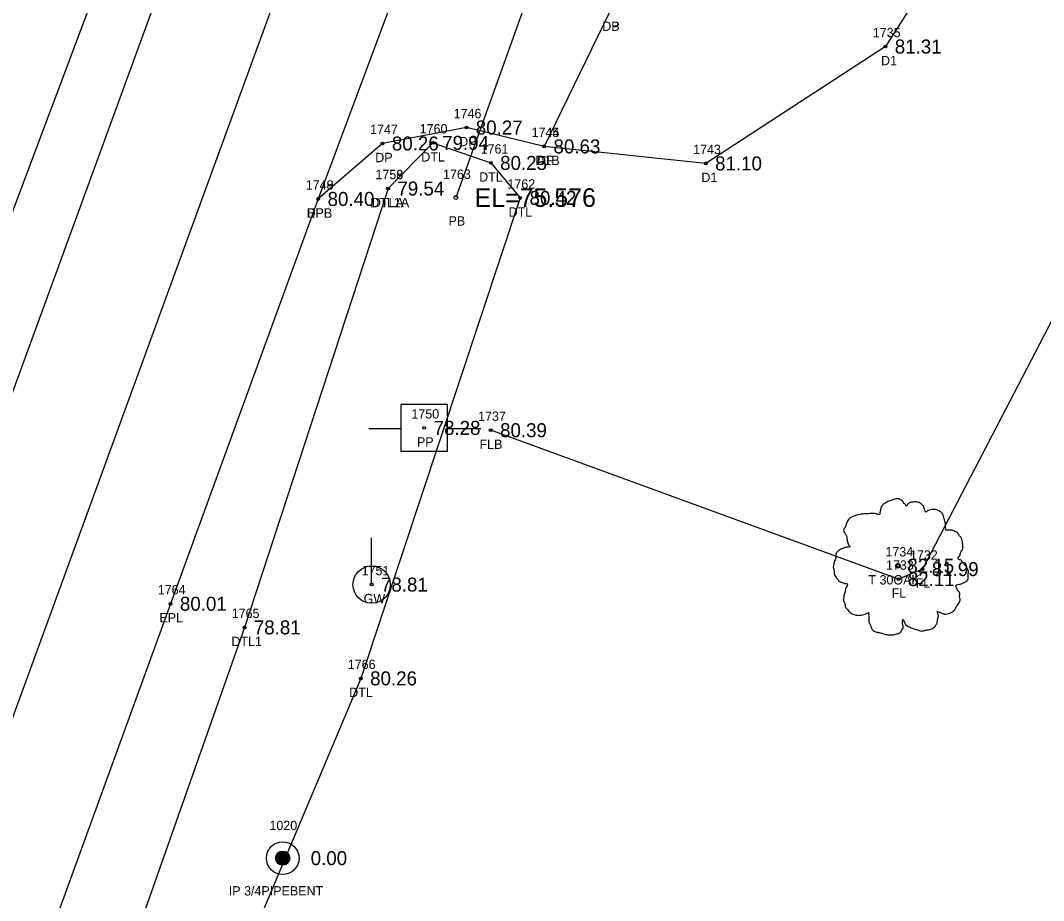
# Model space of a CAD drawing. Extents: x 2139392 to 2143384, y 505395 to 510520.
# Drawn here: x 2141070.2 to 2141179.8, y 509339.5 to 509433.7 of the extents above; entities that cross this region are included whole.
import ezdxf

# ---------------------------------------------------------------- set-up
doc = ezdxf.new("R2010")
doc.units = 0
for name, color, linetype in [('RD_EX_DR_Pipe', 7, 'Continuous'), ('RD_EX_DR_Pipe_txCode', 7, 'Continuous'), ('RD_EX_Driveway', 7, 'Continuous'), ('RD_EX_Driveway_txCode', 7, 'Continuous'), ('RD_EX_DV_Prop_txCode', 7, 'Continuous'), ('RD_EX_DV_PropPin', 7, 'Continuous'), ('RD_EX_Fence_Other', 7, 'Continuous'), ('RD_EX_Fence_Other_txCode', 7, 'Continuous'), ('RD_EX_H2O', 7, 'Continuous'), ('RD_EX_H2O_txCode', 7, 'Continuous'), ('RD_EX_Road', 7, 'Continuous'), ('RD_EX_Road_txCode', 7, 'Continuous'), ('RD_EX_TX_Driveway_ELEV', 7, 'Continuous'), ('RD_EX_TX_DV_Prop_ELEV', 7, 'Continuous'), ('RD_EX_TX_Fence_Other_ELEV', 7, 'Continuous'), ('RD_EX_TX_H2O_ELEV', 7, 'Continuous'), ('RD_EX_TX_Road_ELEV', 7, 'Continuous'), ('RD_EX_TX_UT_ELEV', 7, 'Continuous'), ('RD_EX_TX_VEG_ELEV', 7, 'Continuous'), ('RD_EX_UT', 7, 'Continuous'), ('RD_EX_UT_txCode', 7, 'Continuous'), ('RD_EX_VEG', 7, 'Continuous'), ('RD_EX_VEG_txCode', 7, 'Continuous'), ('RD_HC_Cl', 7, 'Continuous'), ('RD_HC_Survey_ELEV', 7, 'Continuous'), ('RD_SMD_Locator', 7, 'Continuous'), ('RD_TX_Pipe_ElevEX', 7, 'Continuous')]:
    doc.layers.add(name, color=color, linetype=linetype)

msp = doc.modelspace()

# ---------------------------------------------------------------- linework, layer by layer
at = {"layer": 'RD_EX_DR_Pipe'}
msp.add_line((2141127.21, 509443.68), (2141116.83, 509414.76), dxfattribs=at)
at = {"layer": 'RD_EX_Driveway'}
for points in [[(2141332.97, 509478.52), (2141281.25, 509505.33), (2141235.66, 509512.77), (2141218.34, 509505.03), (2141189.33, 509472.4), (2141162.86, 509430.93), (2141143.61, 509418.42), (2141126.3, 509420.24)], [(2141115.5, 509450.65), (2141123.22, 509439.59), (2141133.3, 509434.61), (2141126.3, 509420.24), (2141117.97, 509422.26), (2141108.98, 509420.55), (2141102.09, 509414.61)]]:
    msp.add_lwpolyline(points, dxfattribs=at)
at = {"layer": 'RD_EX_DV_PropPin'}
for p, q in [((2141098.07, 509343.3), (2141098.07, 509344.76)), ((2141098.11, 509343.29), (2141098.11, 509344.77)), ((2141098.14, 509343.28), (2141098.14, 509344.78)), ((2141098.18, 509343.28), (2141098.18, 509344.79)), ((2141098.21, 509343.27), (2141098.21, 509344.79)), ((2141098.25, 509343.27), (2141098.25, 509344.79)), ((2141098.28, 509343.27), (2141098.28, 509344.79)), ((2141098.32, 509343.27), (2141098.32, 509344.79)), ((2141098.35, 509343.27), (2141098.35, 509344.79)), ((2141098.39, 509343.28), (2141098.39, 509344.79)), ((2141098.42, 509343.28), (2141098.42, 509344.78)), ((2141098.46, 509343.29), (2141098.46, 509344.77)), ((2141098.49, 509343.3), (2141098.49, 509344.76)), ((2141097.55, 509343.84), (2141097.55, 509344.23)), ((2141097.58, 509343.73), (2141097.58, 509344.33)), ((2141097.62, 509343.66), (2141097.62, 509344.4)), ((2141097.65, 509343.61), (2141097.65, 509344.46)), ((2141097.69, 509343.56), (2141097.69, 509344.51)), ((2141097.72, 509343.52), (2141097.72, 509344.55)), ((2141097.76, 509343.48), (2141097.76, 509344.58)), ((2141097.79, 509343.45), (2141097.79, 509344.61)), ((2141097.83, 509343.42), (2141097.83, 509344.64)), ((2141097.86, 509343.4), (2141097.86, 509344.67)), ((2141097.9, 509343.38), (2141097.9, 509344.69)), ((2141097.93, 509343.36), (2141097.93, 509344.71)), ((2141097.97, 509343.34), (2141097.97, 509344.73)), ((2141098, 509343.33), (2141098, 509344.74)), ((2141098.04, 509343.31), (2141098.04, 509344.75)), ((2141098.53, 509343.31), (2141098.53, 509344.75)), ((2141098.56, 509343.33), (2141098.56, 509344.74)), ((2141098.6, 509343.34), (2141098.6, 509344.73)), ((2141098.63, 509343.36), (2141098.63, 509344.71)), ((2141098.67, 509343.38), (2141098.67, 509344.69)), ((2141098.7, 509343.4), (2141098.7, 509344.67)), ((2141098.74, 509343.42), (2141098.74, 509344.64)), ((2141098.77, 509343.45), (2141098.77, 509344.61)), ((2141098.81, 509343.48), (2141098.81, 509344.58)), ((2141098.84, 509343.52), (2141098.84, 509344.55)), ((2141098.88, 509343.56), (2141098.88, 509344.51)), ((2141098.91, 509343.61), (2141098.91, 509344.46)), ((2141098.95, 509343.66), (2141098.95, 509344.4)), ((2141098.98, 509343.73), (2141098.98, 509344.33)), ((2141099.02, 509343.84), (2141099.02, 509344.23))]:
    msp.add_line(p, q, dxfattribs=at)
for radius in [1.75, 0.761]:
    msp.add_circle((2141098.28, 509344.03), radius, dxfattribs=at)
at = {"layer": 'RD_EX_Fence_Other'}
msp.add_lwpolyline([(2141244.96, 509535.08), (2141227.83, 509492.25), (2141166.83, 509374.98), (2141164.26, 509373.91), (2141120.57, 509389.85)], dxfattribs=at)
at = {"layer": 'RD_EX_H2O'}
for points in [[(2141076.89, 509480.34), (2141083.49, 509479.19), (2141090.32, 509475.51), (2141090.18, 509468.83), (2141057.26, 509381.22), (2141044.55, 509348.8)], [(2141109.57, 509415.73), (2141114.37, 509420.62), (2141120.58, 509418.47), (2141123.73, 509414.72), (2141106.65, 509363.28), (2141087.87, 509318.68), (2141079.16, 509303.21), (2141069.29, 509273.89), (2141065.76, 509268.54), (2141032.31, 509171.57), (2140998.87, 509079.36), (2140999.1, 509067.34)], [(2141109.57, 509415.73), (2141094.19, 509368.74), (2141059.48, 509270.33), (2141024.5, 509174.17), (2140991.17, 509081.19), (2140987.7, 509072.11)]]:
    msp.add_lwpolyline(points, dxfattribs=at)
at = {"layer": 'RD_EX_Road'}
for points in [[(2141389.23, 510293.58), (2141374.66, 510243.58), (2141359.1, 510192.72), (2141341.17, 510140.58), (2141322.74, 510087.97), (2141303.61, 510035.12), (2141287.18, 509990.16), (2141276.99, 509962.02), (2141248.91, 509884.35), (2141213.37, 509787.47), (2141207.76, 509772.94), (2141199.35, 509749.36), (2141191.47, 509727.8), (2141175.93, 509686.04), (2141140.09, 509588.3), (2141106.08, 509494.11), (2141096.82, 509469.24), (2141063.82, 509378.98), (2141052.52, 509348.48), (2141043.48, 509323.88)], [(2141412.62, 510288.46), (2141398.29, 510238.16), (2141381.65, 510185.39), (2141379.05, 510176.51), (2141367.08, 510141.57), (2141363.58, 510131.95), (2141345.23, 510080.36), (2141326.05, 510027.03), (2141308.64, 509979.4), (2141271.24, 509876.37), (2141240, 509789.51), (2141233.78, 509773.43), (2141223.56, 509746.41), (2141212.18, 509714.93), (2141204.36, 509694.36), (2141197.99, 509676.56), (2141193.66, 509664.6), (2141161.61, 509577.24), (2141123.75, 509473.61), (2141115.5, 509450.65), (2141102.09, 509414.61), (2141086.27, 509371.27), (2141050.42, 509272.83)]]:
    msp.add_lwpolyline(points, dxfattribs=at)
at = {"layer": 'RD_EX_UT'}
for p, q in [((2141115.94, 509392.61), (2141110.94, 509392.61)), ((2141110.94, 509392.61), (2141110.94, 509387.61)), ((2141115.94, 509387.61), (2141115.94, 509392.61)), ((2141107.51, 509390.04), (2141110.98, 509390.04)), ((2141115.87, 509390.04), (2141119.51, 509390.04)), ((2141110.94, 509387.61), (2141115.94, 509387.61)), ((2141107.81, 509373.32), (2141107.81, 509378.32))]:
    msp.add_line(p, q, dxfattribs=at)
msp.add_circle((2141107.81, 509373.32), 2, dxfattribs=at)
at = {"layer": 'RD_EX_VEG'}
for centre, radius in [((2141164.21, 509375.33), 0.25), ((2141164.2, 509375.31), 0.0001)]:
    msp.add_circle(centre, radius, dxfattribs=at)
for points in [[(2141164.34, 509382.5), (2141164.04, 509382.52), (2141163.72, 509382.42), (2141163.47, 509382.32), (2141163.24, 509382.25), (2141163.02, 509382.15), (2141162.72, 509381.97), (2141162.49, 509381.77), (2141162.37, 509381.52), (2141162.32, 509381.3), (2141162.27, 509381.02), (2141162.27, 509380.85), (2141162.14, 509380.82), (2141161.99, 509380.85), (2141161.74, 509380.92), (2141161.49, 509380.92), (2141161.24, 509380.92), (2141160.89, 509380.9), (2141160.54, 509380.9), (2141160.27, 509380.85), (2141159.94, 509380.8), (2141159.57, 509380.67), (2141159.22, 509380.55), (2141158.92, 509380.3), (2141158.67, 509379.82), (2141158.54, 509379.47), (2141158.39, 509379.22), (2141158.54, 509378.77), (2141158.72, 509378.42), (2141158.74, 509378.22), (2141158.82, 509377.8), (2141158.92, 509377.57), (2141159.04, 509377.37), (2141158.97, 509377.35), (2141158.59, 509377.3), (2141158.29, 509377.2), (2141157.87, 509376.97), (2141157.64, 509376.75), (2141157.54, 509376.42), (2141157.52, 509376.07), (2141157.42, 509375.87), (2141157.34, 509375.6), (2141157.32, 509375.52), (2141157.27, 509375.2), (2141157.37, 509374.75), (2141157.39, 509374.4), (2141157.52, 509374.18), (2141157.67, 509374), (2141157.84, 509373.75), (2141158.24, 509373.53), (2141158.57, 509373.43), (2141158.77, 509373.4), (2141158.59, 509372.9), (2141158.54, 509372.55), (2141158.42, 509372.15), (2141158.42, 509372.08), (2141158.37, 509371.6), (2141158.52, 509371.28), (2141158.59, 509370.9), (2141158.77, 509370.68), (2141159.04, 509370.38), (2141159.37, 509370.15), (2141159.87, 509370.03), (2141160.27, 509370.05), (2141160.84, 509370.23), (2141161.09, 509370.3), (2141161.07, 509370.13), (2141161.09, 509369.75), (2141161.09, 509369.33), (2141161.24, 509369), (2141161.34, 509368.73), (2141161.49, 509368.48), (2141161.82, 509368.25), (2141162.22, 509368.18), (2141162.64, 509368.03), (2141163.09, 509367.95), (2141163.59, 509367.93), (2141164.19, 509368.08), (2141164.47, 509368.2), (2141164.57, 509368.38), (2141164.77, 509368.75), (2141164.72, 509368.98), (2141164.74, 509369.58), (2141164.84, 509369.4), (2141165.02, 509369.05), (2141165.52, 509368.75), (2141165.91, 509368.58), (2141166.39, 509368.43), (2141166.69, 509368.35), (2141167.16, 509368.43), (2141167.54, 509368.5), (2141167.91, 509368.63), (2141168.21, 509368.9), (2141168.39, 509369.18), (2141168.44, 509369.45), (2141168.51, 509369.83), (2141168.56, 509370)], [(2141168.56, 509370), (2141168.49, 509370.18), (2141168.44, 509370.43), (2141168.51, 509370.4), (2141168.69, 509370.35), (2141168.96, 509370.23), (2141169.19, 509370.15), (2141169.51, 509370.18), (2141169.79, 509370.28), (2141170.24, 509370.55), (2141170.51, 509371.03), (2141170.79, 509371.43), (2141170.86, 509371.75), (2141170.81, 509371.98), (2141170.79, 509372.48), (2141170.59, 509372.73), (2141170.54, 509372.85), (2141170.44, 509373.25), (2141170.51, 509373.3), (2141170.79, 509373.35), (2141171.16, 509373.48), (2141171.44, 509373.6), (2141171.66, 509373.78), (2141171.74, 509374), (2141171.71, 509374.4), (2141171.76, 509374.8), (2141171.69, 509374.95), (2141171.59, 509375.1), (2141171.51, 509375.3), (2141171.36, 509375.45), (2141171.26, 509375.6), (2141171.16, 509375.7), (2141171.04, 509375.85), (2141170.86, 509375.97), (2141170.71, 509376.02), (2141170.66, 509376.17), (2141170.81, 509376.37), (2141170.86, 509376.47), (2141170.89, 509376.7), (2141171.11, 509377.05), (2141171.16, 509377.45), (2141171.11, 509377.87), (2141171.06, 509378.15), (2141170.91, 509378.42), (2141170.71, 509378.67), (2141170.59, 509378.85), (2141170.41, 509378.97), (2141170.09, 509379.1), (2141169.84, 509379.15), (2141169.49, 509379.15), (2141169.29, 509379.2), (2141169.31, 509379.25), (2141169.31, 509379.4), (2141169.31, 509379.67), (2141169.24, 509380.12), (2141169.09, 509380.62), (2141169.09, 509380.65), (2141168.99, 509380.9), (2141168.76, 509381.1), (2141168.59, 509381.2), (2141168.39, 509381.32), (2141168.14, 509381.35), (2141167.84, 509381.35), (2141167.56, 509381.3), (2141167.36, 509381.2), (2141167.19, 509381.07), (2141167.11, 509381.22), (2141167.01, 509381.52), (2141166.96, 509381.67), (2141166.81, 509381.85), (2141166.59, 509382.05), (2141166.14, 509382.17), (2141165.52, 509382.1), (2141165.22, 509381.9), (2141165.07, 509381.72), (2141165.02, 509381.85), (2141164.82, 509382.05), (2141164.72, 509382.22), (2141164.54, 509382.35), (2141164.39, 509382.45), (2141164.29, 509382.5)]]:
    msp.add_spline(points, degree=3, dxfattribs=at)
at = {"layer": 'RD_HC_Cl'}
msp.add_line((2141333.53, 510081.69), (2140670.51, 508268.37), dxfattribs=at)
at = {"layer": 'RD_SMD_Locator'}
for centre, radius in [((2141162.86, 509430.93), 0.15), ((2141117.97, 509422.26), 0.15), ((2141108.98, 509420.55), 0.15), ((2141114.37, 509420.62), 0.15), ((2141126.3, 509420.24), 0.15), ((2141126.3, 509420.24), 0.15), ((2141120.58, 509418.47), 0.15), ((2141143.61, 509418.42), 0.15), ((2141109.57, 509415.73), 0.15), ((2141109.57, 509415.73), 0.15), ((2141116.83, 509414.76), 0.2), ((2141102.09, 509414.61), 0.15), ((2141102.09, 509414.61), 0.15), ((2141123.73, 509414.72), 0.15), ((2141113.45, 509390.1), 0.15), ((2141120.57, 509389.85), 0.15), ((2141164.21, 509375.33), 0.15), ((2141166.83, 509374.98), 0.15), ((2141107.81, 509373.32), 0.15), ((2141164.26, 509373.91), 0.15), ((2141086.27, 509371.27), 0.15), ((2141094.19, 509368.74), 0.15), ((2141106.65, 509363.28), 0.15), ((2141098.28, 509344.03), 0.15)]:
    msp.add_circle(centre, radius, dxfattribs=at)

# ---------------------------------------------------------------- texts
at = {"layer": 'RD_EX_DR_Pipe_txCode'}
for s, p in [('1763', (2141115.46, 509416.76)), ('PB', (2141116.05, 509411.76))]:
    msp.add_text(s, height=1, dxfattribs=at).set_placement(p)
at = {"layer": 'RD_EX_Driveway_txCode'}
for s, p in [('DP', (2141132.52, 509432.61)), ('DB', (2141132.52, 509432.61)), ('1735', (2141161.51, 509431.93)), ('D1', (2141162.39, 509428.93)), ('1746', (2141116.6, 509423.26)), ('1747', (2141107.64, 509421.55)), ('1744', (2141124.95, 509421.24)), ('1745', (2141124.95, 509421.24)), ('DP', (2141117.19, 509420.26)), ('1743', (2141142.26, 509419.42)), ('DP', (2141108.2, 509418.55)), ('D1B', (2141125.35, 509418.24)), ('DP', (2141125.52, 509418.24)), ('D1', (2141143.14, 509416.42)), ('1748', (2141100.75, 509415.61)), ('DPB', (2141100.84, 509412.61))]:
    msp.add_text(s, height=1, dxfattribs=at).set_placement(p)
at = {"layer": 'RD_EX_DV_Prop_txCode'}
for s, p in [('1020', (2141096.86, 509347.03)), ('IP 3/4PIPEBENT', (2141092.51, 509340.03))]:
    msp.add_text(s, height=1, dxfattribs=at).set_placement(p)
at = {"layer": 'RD_EX_Fence_Other_txCode'}
for s, p in [('1737', (2141119.22, 509390.85)), ('FLB', (2141119.37, 509387.85)), ('1732', (2141165.49, 509375.98)), ('1733', (2141162.92, 509374.91)), ('FL', (2141166.1, 509372.98)), ('FL', (2141163.53, 509371.91))]:
    msp.add_text(s, height=1, dxfattribs=at).set_placement(p)
at = {"layer": 'RD_EX_H2O_txCode'}
for s, p in [('1760', (2141112.96, 509421.62)), ('1761', (2141119.49, 509419.47)), ('DTL', (2141113.13, 509418.62)), ('1758', (2141108.22, 509416.73)), ('1759', (2141108.22, 509416.73)), ('DTL', (2141119.33, 509416.47)), ('1762', (2141122.36, 509415.72)), ('DTL1A', (2141107.67, 509413.73)), ('DTLA', (2141107.84, 509413.73)), ('DTL', (2141122.49, 509412.72)), ('1765', (2141092.82, 509369.74)), ('DTL1', (2141092.78, 509366.74)), ('1766', (2141105.26, 509364.28)), ('DTL', (2141105.41, 509361.28))]:
    msp.add_text(s, height=1, dxfattribs=at).set_placement(p)
at = {"layer": 'RD_EX_Road_txCode'}
for s, p in [('1749', (2141100.75, 509415.61)), ('EPL', (2141100.89, 509412.61)), ('1764', (2141084.9, 509372.27)), ('EPL', (2141085.07, 509369.27))]:
    msp.add_text(s, height=1, dxfattribs=at).set_placement(p)
at = {"layer": 'RD_EX_TX_Driveway_ELEV'}
for s, p in [('81.31', (2141163.86, 509430.18)), ('80.27', (2141118.97, 509421.51)), ('80.26', (2141109.98, 509419.8)), ('80.63', (2141127.3, 509419.49)), ('80.63', (2141127.3, 509419.49)), ('81.10', (2141144.61, 509417.67)), ('80.40', (2141103.09, 509413.86))]:
    msp.add_text(s, height=1.5, dxfattribs=at).set_placement(p)
at = {"layer": 'RD_EX_TX_DV_Prop_ELEV'}
msp.add_text('0.00', height=1.5, dxfattribs=at).set_placement((2141101.28, 509343.28))
at = {"layer": 'RD_EX_TX_Fence_Other_ELEV'}
for s, p in [('80.39', (2141121.57, 509389.1)), ('81.99', (2141167.83, 509374.23)), ('82.11', (2141165.26, 509373.16))]:
    msp.add_text(s, height=1.5, dxfattribs=at).set_placement(p)
at = {"layer": 'RD_EX_TX_H2O_ELEV'}
for s, p in [('79.94', (2141115.37, 509419.87)), ('80.25', (2141121.58, 509417.72)), ('79.54', (2141110.57, 509414.98)), ('79.54', (2141110.57, 509414.98)), ('80.42', (2141124.73, 509413.97)), ('78.81', (2141095.19, 509367.99)), ('80.26', (2141107.65, 509362.53))]:
    msp.add_text(s, height=1.5, dxfattribs=at).set_placement(p)
at = {"layer": 'RD_EX_TX_Road_ELEV'}
for s, p in [('80.40', (2141103.09, 509413.86)), ('80.01', (2141087.27, 509370.52))]:
    msp.add_text(s, height=1.5, dxfattribs=at).set_placement(p)
at = {"layer": 'RD_EX_TX_UT_ELEV'}
msp.add_text('78.81', height=1.5, dxfattribs=at).set_placement((2141108.81, 509372.57))
at = {"layer": 'RD_EX_TX_VEG_ELEV'}
msp.add_text('82.15', height=1.5, dxfattribs=at).set_placement((2141165.21, 509374.58))
at = {"layer": 'RD_EX_UT_txCode'}
for s, p in [('1750', (2141112.07, 509391.1)), ('PP', (2141112.67, 509388.1)), ('1751', (2141106.74, 509374.32)), ('GW', (2141106.96, 509371.32))]:
    msp.add_text(s, height=1, dxfattribs=at).set_placement(p)
at = {"layer": 'RD_EX_VEG_txCode'}
for s, p in [('1734', (2141162.86, 509376.33)), ('T 30OAK', (2141161.04, 509373.33))]:
    msp.add_text(s, height=1, dxfattribs=at).set_placement(p)
at = {"layer": 'RD_HC_Survey_ELEV'}
msp.add_text('78.28', height=1.5, dxfattribs=at).set_placement((2141114.45, 509389.35))
at = {"layer": 'RD_TX_Pipe_ElevEX'}
msp.add_text('EL=75.576', height=2, dxfattribs=at).set_placement((2141118.83, 509413.76))

doc.saveas('drawing.dxf')
